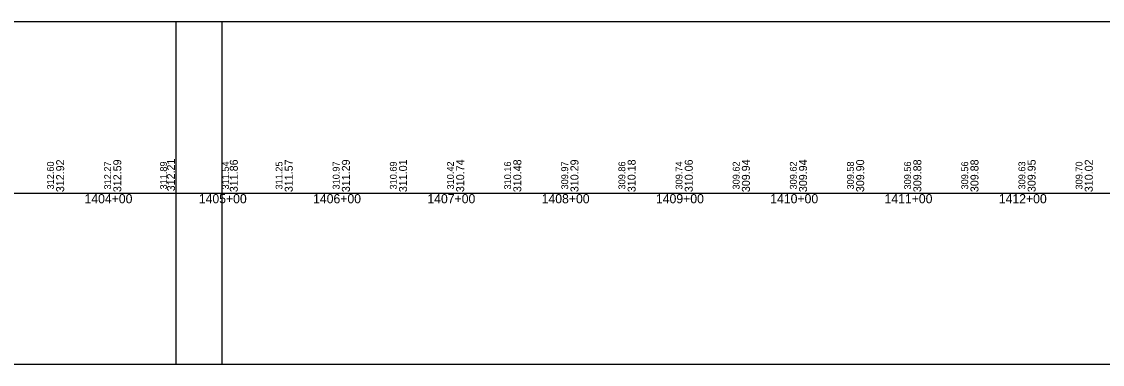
# Model space of a CAD drawing. Extents: x -3627 to 47473, y 2850 to 4350.
# Drawn here: x 27798 to 28744, y 2850 to 3150 of the extents above; entities that cross this region are included whole.
import ezdxf

# ---------------------------------------------------------------- set-up
doc = ezdxf.new("R2010")
doc.units = 0
for name, color, linetype in [('RD_DDB_StaTX', 7, 'Continuous'), ('RD_DDB_StripGrade', 7, 'Continuous'), ('RD_GPK_Profile_Cell', 7, 'Continuous'), ('RD_SHT_ShtClip', 7, 'Continuous')]:
    doc.layers.add(name, color=color, linetype=linetype)

msp = doc.modelspace()

# ---------------------------------------------------------------- linework, layer by layer
at = {"layer": 'RD_GPK_Profile_Cell'}
msp.add_line((1000, 3000), (46705.077602, 3000), dxfattribs=at)
at = {"layer": 'RD_SHT_ShtClip'}
for points in [[(26433.33, 3150), (27973.33, 3150), (27973.33, 2850), (26433.33, 2850)], [(27933.33, 3150), (29473.33, 3150), (29473.33, 2850), (27933.33, 2850)]]:
    msp.add_lwpolyline(points, close=True, dxfattribs=at)

# ---------------------------------------------------------------- texts
at = {"layer": 'RD_DDB_StaTX'}
for s, p in [('1404+00', (27853.125471, 2991)), ('1405+00', (27953.125471, 2991)), ('1406+00', (28053.125471, 2991)), ('1407+00', (28153.125471, 2991)), ('1408+00', (28253.125471, 2991)), ('1409+00', (28353.125471, 2991)), ('1410+00', (28453.125471, 2991)), ('1411+00', (28553.125471, 2991)), ('1412+00', (28653.125471, 2991))]:
    msp.add_text(s, height=8, dxfattribs=at).set_placement(p)
at = {"layer": 'RD_DDB_StripGrade'}
for s, height, p in [('312.60', 6, (27826.33, 3003.073688)), ('312.92', 7, (27835.33, 3000.75)), ('312.27', 6, (27876.33, 3003.073688)), ('312.59', 7, (27885.33, 3000.75)), ('311.89', 6, (27925.274544, 3003.073688)), ('312.21', 7, (27932.274544, 3001.487018)), ('311.54', 6, (27979.508594, 3003.073688)), ('311.86', 7, (27987.255702, 3000.75)), ('311.25', 6, (28026.33, 3003.073688)), ('311.57', 7, (28035.33, 3000.75)), ('310.97', 6, (28076.33, 3003.073688)), ('311.29', 7, (28085.33, 3000.75)), ('310.69', 6, (28126.33, 3003.073688)), ('311.01', 7, (28135.33, 3000.75)), ('310.42', 6, (28176.33, 3003.073688)), ('310.74', 7, (28185.33, 3000.75)), ('310.16', 6, (28226.33, 3003.073688)), ('310.48', 7, (28235.33, 3000.75)), ('309.97', 6, (28276.33, 3003.073688)), ('310.29', 7, (28285.33, 3000.75)), ('309.86', 6, (28326.33, 3003.073688)), ('310.18', 7, (28335.33, 3000.75)), ('309.74', 6, (28376.33, 3003.073688)), ('310.06', 7, (28385.33, 3000.75)), ('309.62', 6, (28426.33, 3003.073688)), ('309.94', 7, (28435.33, 3000.75)), ('309.62', 6, (28476.33, 3003.073688)), ('309.94', 7, (28485.33, 3000.75)), ('309.58', 6, (28526.33, 3003.073688)), ('309.90', 7, (28535.33, 3000.75)), ('309.56', 6, (28576.33, 3003.073688)), ('309.88', 7, (28585.33, 3000.75)), ('309.56', 6, (28626.33, 3003.073688)), ('309.88', 7, (28635.33, 3000.75)), ('309.63', 6, (28676.33, 3003.073688)), ('309.95', 7, (28685.33, 3000.75)), ('309.70', 6, (28726.33, 3003.073688)), ('310.02', 7, (28735.33, 3000.75))]:
    msp.add_text(s, height=height, rotation=90, dxfattribs=at).set_placement(p)

doc.saveas('drawing.dxf')
